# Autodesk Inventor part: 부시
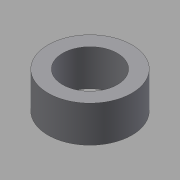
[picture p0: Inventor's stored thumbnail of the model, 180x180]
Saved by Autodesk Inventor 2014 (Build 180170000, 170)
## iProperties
Created: 2015-09
Part Number: 부시
Document SubType Name: Modeling
Designer: mduedu
Density: 1 g/cm^3
Material: 스테인리스강
Appearance: 기본값
Author: mduedu
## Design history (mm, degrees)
node "작업 평면1"
node "작업 평면2"
sketch "스케치1"
  geometry: C1 r 7.5 at (0, 0); C2 r 11.5 at (0, 0); 1 further point
  constraints: 2 centre point, 2 coincident
  dimensions: "d0" = 15 diameter of C1; "d1" = 23 diameter of C2
extrude "돌출1" new body sketch "스케치1" stored distance "d2" = 9.85; taper "d3" = 0 deg
node "솔리드1"
